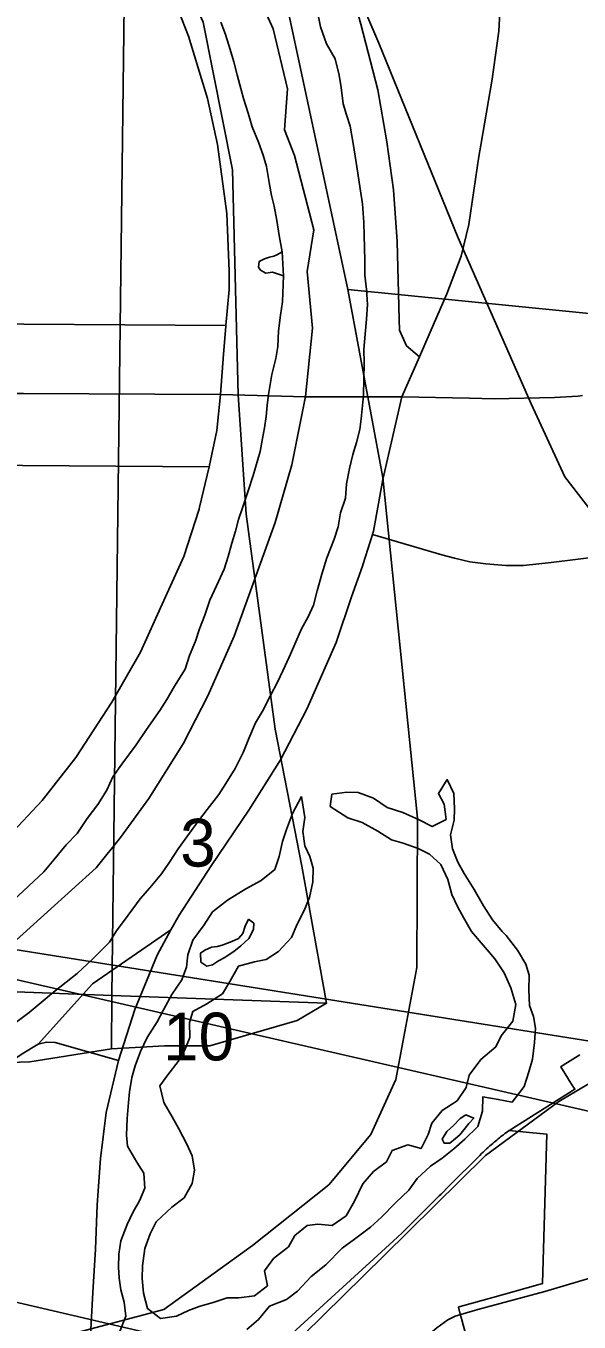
# Model space of a CAD drawing. Extents: x 0 to 34, y 0 to 22.
# Drawn here: x 5.94 to 6.424, y 16.149 to 17.285 of the extents above; entities that cross this region are included whole.
import ezdxf

# ---------------------------------------------------------------- set-up
doc = ezdxf.new("R2010")
doc.units = 0
for name, color, linetype in [('GM_X_City_Street', 7, 'Continuous'), ('GM_X_Corporation', 7, 'Continuous'), ('GM_X_County_Road', 7, 'Continuous'), ('GM_X_Major_River', 7, 'Continuous'), ('GM_X_Minor_Lake', 7, 'Continuous'), ('GM_X_Rail_Line', 7, 'Continuous'), ('GM_X_Section', 7, 'Continuous'), ('GM_X_Section_Text', 7, 'Continuous'), ('GM_X_State_Route', 7, 'Continuous'), ('GM_X_Township_Road', 7, 'Continuous'), ('SH_Text', 7, 'Continuous')]:
    doc.layers.add(name, color=color, linetype=linetype)

msp = doc.modelspace()

# ---------------------------------------------------------------- linework, layer by layer
at = {"layer": 'GM_X_City_Street'}
msp.add_line((6.2692, 16.9601), (6.3283, 16.9588), dxfattribs=at)
for points in [[(6.2667, 17.0282), (6.2651, 17.0961), (6.2619, 17.1413), (6.2559, 17.1835), (6.2479, 17.2291), (6.2332, 17.2866), (6.2208, 17.3307), (6.2057, 17.3695), (6.1994, 17.3856), (6.167, 17.4375), (6.1424, 17.4763), (6.0844, 17.5737), (6.0399, 17.6695), (6.0364, 17.6779), (6.0205, 17.716)], [(6.1148, 17.0215), (6.1149, 17.0225), (6.1177, 17.0542), (6.1178, 17.0702), (6.1157, 17.1206), (6.1076, 17.1813), (6.0989, 17.2215), (6.0821, 17.2761), (6.0569, 17.3412)], [(5.6157, 17.0314), (5.6206, 17.0277), (5.6254, 17.024), (5.6872, 17.0254), (5.8138, 17.025), (5.938, 17.0236), (6.1149, 17.0225)], [(6.1103, 16.9619), (6.1128, 16.9973), (6.1148, 17.0215)], [(6.2845, 16.9951), (6.2733, 17.0046), (6.2669, 17.0183), (6.2667, 17.0282)], [(5.813, 16.9637), (5.9115, 16.9629), (5.9375, 16.9628), (6.1103, 16.9619)], [(6.0919, 16.8634), (6.1003, 16.8985), (6.1069, 16.9304), (6.1103, 16.9619)], [(6.1103, 16.9619), (6.1849, 16.9599), (6.2692, 16.9601)], [(6.3283, 16.9588), (6.35, 16.9583), (6.4028, 16.9594), (6.4234, 16.9605), (6.4273, 16.9611)], [(5.6258, 16.9043), (5.8116, 16.9012), (5.9368, 16.8998), (6.1003, 16.8985)], [(5.5538, 16.5337), (5.5663, 16.5354), (5.5855, 16.5344), (5.5977, 16.5337), (5.606, 16.5333), (5.7039, 16.5242), (5.7775, 16.52), (5.8216, 16.5178), (5.8447, 16.5199), (5.8678, 16.5304), (5.8867, 16.543), (5.9245, 16.5746), (5.954, 16.6061), (5.9834, 16.6439), (6.0149, 16.6922), (6.0401, 16.7363), (6.059, 16.7783), (6.078, 16.8199), (6.0914, 16.8614), (6.0919, 16.8634)], [(6.2435, 16.8392), (6.304, 16.8215), (6.3153, 16.8187), (6.3285, 16.8154), (6.3427, 16.8135), (6.3601, 16.8121), (6.3757, 16.8121), (6.3998, 16.8149), (6.4852, 16.8253), (6.5792, 16.8385)], [(6.0668, 16.4928), (5.9982, 16.4455), (5.9505, 16.3926)], [(5.2425, 16.2183), (5.2513, 16.2216), (5.2602, 16.2223), (5.2843, 16.2201), (5.3467, 16.2161), (5.4122, 16.2135), (5.4393, 16.2119), (5.4499, 16.2113), (5.4915, 16.2125), (5.5278, 16.2165), (5.5628, 16.2224), (5.6238, 16.2341), (5.6759, 16.2485), (5.7191, 16.2629), (5.7839, 16.2907), (5.8093, 16.3036), (5.8399, 16.3198), (5.8867, 16.349), (5.9181, 16.3715), (5.9366, 16.3841), (5.9505, 16.3926), (5.9577, 16.3944), (5.9654, 16.394), (6.021, 16.3782)], [(6.3432, 16.162), (6.3943, 16.1757), (6.4318, 16.1867), (6.4582, 16.1974), (6.4798, 16.2098), (6.5079, 16.2262), (6.5312, 16.2404), (6.5539, 16.252), (6.5654, 16.2551), (6.577, 16.2574), (6.5936, 16.2577), (6.6025, 16.2574)], [(6.0364, 15.8874), (6.0374, 15.8877), (6.1029, 15.909), (6.1175, 15.9145), (6.1293, 15.9201), (6.1457, 15.9324), (6.1594, 15.9456), (6.1736, 15.9638), (6.2061, 16.0119), (6.2305, 16.0456), (6.2615, 16.0919), (6.2892, 16.1327), (6.294, 16.1389), (6.2996, 16.1438), (6.3093, 16.151), (6.3158, 16.1541), (6.3355, 16.1599), (6.3432, 16.162)]]:
    msp.add_lwpolyline(points, dxfattribs=at)
at = {"layer": 'GM_X_Corporation'}
msp.add_lwpolyline([(6.3291, 16.1231), (6.322, 16.1496), (6.3218, 16.15), (6.3203, 16.1558), (6.3203, 16.1559), (6.3186, 16.162), (6.3193, 16.1623), (6.3201, 16.1625), (6.3488, 16.1705), (6.3882, 16.1815), (6.3922, 16.1827), (6.3952, 16.2836), (6.3958, 16.304), (6.3961, 16.3136), (6.3808, 16.3152), (6.3632, 16.317), (6.3651, 16.3181), (6.3692, 16.3207), (6.3748, 16.3243), (6.4207, 16.353), (6.419, 16.3556), (6.4152, 16.3617), (6.4152, 16.3618), (6.4145, 16.3628), (6.4083, 16.3728), (6.4103, 16.374), (6.4103, 16.374), (6.4251, 16.3833)], dxfattribs=at)
at = {"layer": 'GM_X_County_Road'}
msp.add_line((6.2853, 16.997), (6.2938, 17.0166), dxfattribs=at)
for points in [[(6.3382, 17.1806), (6.3481, 17.2383), (6.3541, 17.2805), (6.3564, 17.3255), (6.3577, 17.3607), (6.3586, 17.3855), (6.3588, 17.3905)], [(6.2938, 17.0166), (6.3084, 17.0502), (6.3209, 17.0833), (6.3278, 17.1109), (6.3365, 17.1706), (6.3382, 17.1806)], [(6.2441, 16.8422), (6.2525, 16.8876), (6.2692, 16.9601), (6.2845, 16.9951), (6.2853, 16.997)], [(6.2353, 16.8135), (6.2435, 16.8392), (6.2441, 16.8422)], [(5.9955, 16.1334), (5.9962, 16.1373), (5.9985, 16.1748), (6.0008, 16.2128), (6.0023, 16.2516), (6.0052, 16.2923), (6.0102, 16.3326), (6.021, 16.3782), (6.0353, 16.4229), (6.0546, 16.4706), (6.0668, 16.4928), (6.0739, 16.5057), (6.102, 16.5489), (6.135, 16.5976), (6.1627, 16.6419), (6.1859, 16.6862), (6.2115, 16.7447), (6.2251, 16.7847), (6.2347, 16.8116), (6.2353, 16.8135)]]:
    msp.add_lwpolyline(points, dxfattribs=at)
at = {"layer": 'GM_X_Major_River'}
msp.add_line((6.1653, 17.0661), (6.1642, 17.087), dxfattribs=at)
for points in [[(5.9426, 16.4203), (5.953, 16.4292), (5.9638, 16.4381), (5.975, 16.447), (5.9846, 16.4544), (5.9981, 16.4671), (6.0129, 16.482), (6.0191, 16.4918), (6.0292, 16.5056), (6.0398, 16.5199), (6.0483, 16.5296), (6.0584, 16.5419), (6.0654, 16.5521), (6.0732, 16.5637), (6.083, 16.5776), (6.0908, 16.5884), (6.0986, 16.5982), (6.1087, 16.6113), (6.115, 16.6211), (6.1232, 16.6342), (6.1303, 16.6489), (6.1351, 16.6606), (6.141, 16.6741), (6.1469, 16.6843), (6.1536, 16.6975), (6.1603, 16.7103), (6.167, 16.7242), (6.1714, 16.7344), (6.1762, 16.7453), (6.1813, 16.7566), (6.1869, 16.7672), (6.1916, 16.7773), (6.1949, 16.7898), (6.199, 16.8046), (6.2034, 16.8189), (6.2098, 16.8351), (6.2134, 16.8461), (6.2152, 16.8582), (6.2196, 16.8711), (6.2206, 16.8836), (6.2232, 16.8972), (6.226, 16.9093), (6.2293, 16.9199), (6.2322, 16.9313), (6.2335, 16.9408), (6.2354, 16.9612), (6.236, 16.9898), (6.2358, 17.0015), (6.2368, 17.0148), (6.2382, 17.0281), (6.2389, 17.041), (6.238, 17.054), (6.2367, 17.0665), (6.2366, 17.0791), (6.2364, 17.0909), (6.2362, 17.1012), (6.2357, 17.1129), (6.2345, 17.1293), (6.2325, 17.1423), (6.2305, 17.156), (6.2281, 17.1709), (6.2264, 17.1819), (6.2237, 17.1972), (6.2205, 17.2072), (6.2176, 17.2167), (6.216, 17.2312), (6.2143, 17.2419), (6.2108, 17.2564), (6.2031, 17.2695), (6.1977, 17.2844), (6.1953, 17.2974)], [(6.1105, 17.2884), (6.1145, 17.2777), (6.1188, 17.2643), (6.122, 17.2536), (6.1248, 17.2421), (6.1304, 17.2215), (6.1344, 17.2085), (6.1379, 17.1966), (6.1434, 17.1832), (6.1477, 17.1717), (6.1505, 17.1618), (6.1529, 17.148), (6.155, 17.1366), (6.1571, 17.127), (6.1595, 17.1145), (6.1615, 17.1015), (6.1642, 17.087)], [(6.1642, 17.087), (6.1596, 17.0844), (6.157, 17.0833), (6.1532, 17.0823), (6.1489, 17.0808), (6.144, 17.0786), (6.1435, 17.0737), (6.1453, 17.071), (6.1498, 17.0683), (6.1559, 17.0693), (6.1653, 17.0661)], [(6.1653, 17.0661), (6.1645, 17.0433), (6.1628, 17.0315), (6.161, 17.0178), (6.1604, 17.0042), (6.1586, 16.9936), (6.1553, 16.9796), (6.1523, 16.9621), (6.151, 16.9523), (6.1501, 16.9428), (6.1487, 16.9329), (6.147, 16.9235), (6.1449, 16.9121), (6.1388, 16.8909), (6.1344, 16.8777), (6.1295, 16.8626), (6.1259, 16.8524), (6.1234, 16.8422), (6.1202, 16.8316), (6.1169, 16.8199), (6.1133, 16.8089), (6.1066, 16.7942), (6.101, 16.7818), (6.0966, 16.7686), (6.0918, 16.7565), (6.0882, 16.7459), (6.083, 16.7331), (6.0794, 16.7214), (6.07, 16.7063), (6.0633, 16.6947), (6.057, 16.6849), (6.0453, 16.6684), (6.0363, 16.6549), (6.0239, 16.6381), (6.016, 16.6268), (6.0105, 16.6151), (6.0027, 16.6027), (5.9933, 16.5904), (5.9847, 16.5772), (5.975, 16.5672), (5.9642, 16.5541), (5.9556, 16.5436), (5.9421, 16.5309), (5.9286, 16.5186)], [(5.9218, 16.4047), (5.9426, 16.4203)]]:
    msp.add_lwpolyline(points, dxfattribs=at)
at = {"layer": 'GM_X_Minor_Lake'}
for points in [[(6.3605, 16.4877), (6.3571, 16.4912), (6.3486, 16.5016), (6.3405, 16.5139), (6.3324, 16.5282), (6.3236, 16.542), (6.3181, 16.552), (6.3134, 16.5639), (6.3118, 16.5761), (6.315, 16.589), (6.3152, 16.5988), (6.3147, 16.6122), (6.3089, 16.6244), (6.3011, 16.6124), (6.3062, 16.6028), (6.3078, 16.5895), (6.2956, 16.5833), (6.2843, 16.5892), (6.27, 16.5956), (6.2561, 16.6), (6.2441, 16.6082), (6.2309, 16.6131), (6.221, 16.6133), (6.2077, 16.6116), (6.2064, 16.601), (6.2217, 16.5908), (6.2342, 16.5868), (6.2481, 16.5793), (6.2601, 16.5718), (6.2703, 16.5686), (6.2834, 16.5641), (6.2932, 16.559), (6.3033, 16.55), (6.3095, 16.537), (6.313, 16.5236), (6.3177, 16.5132), (6.3232, 16.5036), (6.3302, 16.4913), (6.3421, 16.4774), (6.3506, 16.4674), (6.3587, 16.455), (6.3645, 16.442), (6.3688, 16.4274), (6.3662, 16.4127), (6.3561, 16.3999), (6.3514, 16.3902), (6.3383, 16.379), (6.3281, 16.3655), (6.3253, 16.3545), (6.3175, 16.3429), (6.3044, 16.3344), (6.2954, 16.3232), (6.2922, 16.3134), (6.2859, 16.301), (6.2742, 16.3042), (6.2605, 16.2992), (6.2557, 16.2894), (6.2442, 16.2809), (6.2348, 16.27), (6.2277, 16.255), (6.2203, 16.2422), (6.208, 16.2337), (6.1955, 16.2347), (6.186, 16.2337), (6.1752, 16.2248), (6.1697, 16.215), (6.1566, 16.2046), (6.1488, 16.1938), (6.1515, 16.1808), (6.14, 16.1719), (6.1263, 16.1703), (6.116, 16.1701), (6.1046, 16.1665), (6.0916, 16.1626), (6.0821, 16.159), (6.0717, 16.1542), (6.0577, 16.1522), (6.0464, 16.1608), (6.0429, 16.1742), (6.0416, 16.1871), (6.0419, 16.1982), (6.044, 16.2133), (6.0485, 16.2262), (6.054, 16.2367), (6.0675, 16.2497), (6.0783, 16.2579), (6.0854, 16.2703), (6.0875, 16.2821), (6.0855, 16.2946), (6.0807, 16.305), (6.0738, 16.3184), (6.0679, 16.3288), (6.0606, 16.3415), (6.0571, 16.356), (6.0641, 16.3658), (6.073, 16.3774), (6.0789, 16.3875), (6.0833, 16.3985), (6.0832, 16.4114), (6.086, 16.4212), (6.0983, 16.4278)], [(6.1811, 16.6095), (6.1733, 16.5948), (6.1681, 16.5808), (6.1644, 16.5703), (6.1615, 16.557), (6.1579, 16.5457), (6.1459, 16.536), (6.1325, 16.5287), (6.1164, 16.5187), (6.1033, 16.5084), (6.0959, 16.4971), (6.0861, 16.4836), (6.0817, 16.4708), (6.0803, 16.4601), (6.0763, 16.4488), (6.0677, 16.4361), (6.0603, 16.4225), (6.0547, 16.412), (6.0461, 16.3985), (6.0402, 16.386), (6.0354, 16.3736), (6.0325, 16.3634), (6.0304, 16.3509), (6.0295, 16.3414), (6.0284, 16.3273), (6.0278, 16.3129), (6.0287, 16.303), (6.0368, 16.2891), (6.0431, 16.2795), (6.0439, 16.2662), (6.0392, 16.2552), (6.0337, 16.2455), (6.0285, 16.2345), (6.0229, 16.2202), (6.0212, 16.2085), (6.021, 16.197), (6.0215, 16.1875), (6.0229, 16.1772), (6.0257, 16.1665), (6.0273, 16.154), (6.0218, 16.14)], [(6.0983, 16.4278), (6.1121, 16.4367), (6.1184, 16.4476), (6.1259, 16.4608), (6.14, 16.4647), (6.1503, 16.4667), (6.161, 16.4738), (6.1723, 16.4861), (6.1774, 16.4978), (6.1834, 16.5098), (6.1881, 16.5211), (6.1911, 16.5348), (6.1913, 16.5469), (6.1885, 16.5569), (6.1841, 16.5665), (6.1824, 16.579), (6.1842, 16.5912), (6.1811, 16.6095)], [(6.1346, 16.502), (6.1319, 16.496), (6.1299, 16.4896), (6.126, 16.4851), (6.1202, 16.4825), (6.1126, 16.4797), (6.1076, 16.4782), (6.1023, 16.4776), (6.0966, 16.475), (6.0927, 16.4724), (6.0929, 16.4645), (6.0982, 16.4609), (6.1031, 16.462), (6.1085, 16.4657)], [(6.1085, 16.4657), (6.1139, 16.4686), (6.1177, 16.4712), (6.122, 16.4738), (6.1281, 16.4786), (6.1351, 16.4853), (6.139, 16.4932), (6.1395, 16.4985), (6.1346, 16.502)], [(6.1333, 16.1424), (6.1434, 16.1513), (6.1531, 16.1629), (6.168, 16.1687), (6.1776, 16.1761), (6.1896, 16.1888), (6.2024, 16.1992), (6.2167, 16.2137), (6.2275, 16.2215), (6.2417, 16.2322), (6.2513, 16.2408), (6.2634, 16.2535), (6.2753, 16.2647), (6.2824, 16.2748), (6.2943, 16.2856), (6.3043, 16.2926), (6.3147, 16.3008), (6.3244, 16.3093), (6.3356, 16.3205), (6.3397, 16.3337), (6.3399, 16.3463), (6.3535, 16.3441), (6.3656, 16.3416), (6.3761, 16.3554), (6.3802, 16.3683), (6.3834, 16.3793), (6.3852, 16.394), (6.3862, 16.4066), (6.3845, 16.4169), (6.3809, 16.4264), (6.3804, 16.4401), (6.3807, 16.4531), (6.3778, 16.4626), (6.3705, 16.4749), (6.3605, 16.4877)], [(6.3252, 16.3306), (6.3202, 16.3273), (6.3144, 16.3213), (6.3086, 16.3161), (6.3043, 16.3093), (6.3061, 16.3059), (6.311, 16.3058), (6.3161, 16.3099)], [(6.3161, 16.3099), (6.3199, 16.3132), (6.3246, 16.3188), (6.3277, 16.3229), (6.332, 16.3278), (6.3252, 16.3306)]]:
    msp.add_lwpolyline(points, dxfattribs=at)
at = {"layer": 'GM_X_Rail_Line'}
for points in [[(6.4409, 16.8524), (6.4119, 16.8899), (6.3824, 16.9538), (6.3182, 17.1), (6.2489, 17.2701), (6.1917, 17.404), (6.1478, 17.4778), (6.1062, 17.5367), (6.0851, 17.5704), (6.0495, 17.6501), (5.9772, 17.794), (5.9463, 17.8569), (5.94, 17.8766), (5.9404, 17.8883), (5.9424, 17.8993), (5.9505, 17.9228), (5.9579, 17.9295), (5.9682, 17.9321), (5.9914, 17.9329), (6.0459, 17.919), (6.0834, 17.9142), (6.1264, 17.9184), (6.1909, 17.9323), (6.2268, 17.9396)], [(6.165, 16.1203), (6.2534, 16.207), (6.3425, 16.2949), (6.4066, 16.3422), (6.4661, 16.3777), (6.5056, 16.3891), (6.5675, 16.4045), (6.5893, 16.4128), (6.6117, 16.4363), (6.6216, 16.4868), (6.6133, 16.6376), (6.5924, 16.7713)]]:
    msp.add_lwpolyline(points, dxfattribs=at)
at = {"layer": 'GM_X_Section'}
for points in [[(6.1181, 18.0687), (7.0966, 17.983), (7.0031, 16.9763), (6.2217, 17.0542), (6.1566, 17.3584), (6.0732, 17.5126)], [(5.0461, 17.3925), (6.0266, 17.3737), (6.0151, 16.4351), (5.016, 16.4735)], [(6.0266, 17.3737), (6.0573, 17.3724), (6.0951, 17.2884), (6.1207, 17.1591), (6.1257, 16.9617), (6.1328, 16.8571), (6.1581, 16.6687), (6.1816, 16.5486), (6.2032, 16.4285), (6.0151, 16.4351)], [(6.2217, 17.0542), (7.0031, 16.9763), (6.9063, 15.9571), (5.9113, 16.0496), (5.9234, 16.1293), (5.9728, 16.1367), (6.0607, 16.16), (6.1382, 16.2162), (6.2051, 16.2691), (6.2419, 16.3134), (6.2637, 16.3615), (6.2822, 16.4596), (6.2827, 16.5907), (6.2524, 16.8893)], [(5.0144, 16.4489), (5.016, 16.4735), (6.0151, 16.4351), (6.0146, 16.3885), (5.9432, 16.377), (5.8075, 16.3727), (5.6552, 16.351), (5.5604, 16.3194), (5.487, 16.3238), (5.3526, 16.3472), (5.2613, 16.3655), (5.1009, 16.4163)], [(6.0151, 16.4351), (6.2032, 16.4285), (6.1773, 16.4133), (6.1008, 16.3911), (6.0611, 16.3911), (6.0146, 16.3885)]]:
    msp.add_lwpolyline(points, close=True, dxfattribs=at)
at = {"layer": 'GM_X_State_Route'}
msp.add_lwpolyline([(6.163, 16.13), (6.2614, 16.2199), (6.2695, 16.2273), (6.3018, 16.2596), (6.3034, 16.2612), (6.3106, 16.2683), (6.3373, 16.295), (6.3389, 16.2966), (6.3403, 16.2979), (6.3419, 16.2994), (6.3433, 16.3008), (6.3448, 16.3021), (6.3461, 16.3033), (6.3474, 16.3044), (6.3488, 16.3056), (6.35, 16.3066), (6.351, 16.3075), (6.3522, 16.3085), (6.3534, 16.3095), (6.3545, 16.3104), (6.3556, 16.3112), (6.3568, 16.3122), (6.3581, 16.3132), (6.3593, 16.3141), (6.3608, 16.3152), (6.362, 16.3161), (6.3632, 16.317), (6.3651, 16.3181), (6.3692, 16.3207), (6.3748, 16.3243), (6.4207, 16.353), (6.419, 16.3556), (6.4152, 16.3617), (6.4152, 16.3618), (6.4145, 16.3628), (6.4083, 16.3728), (6.4103, 16.374), (6.4251, 16.3833)], dxfattribs=at)
at = {"layer": 'GM_X_Township_Road'}
for points in [[(5.8944, 16.4506), (6.0012, 16.547), (6.0226, 16.5736), (6.0475, 16.6079), (6.0775, 16.6559), (6.099, 16.6979), (6.1221, 16.7502), (6.1581, 16.8497), (6.1727, 16.9003), (6.1846, 16.9604), (6.1907, 17.0203), (6.1862, 17.0698), (6.192, 17.1065), (6.1749, 17.1716), (6.1663, 17.1939), (6.1689, 17.2299), (6.1564, 17.2827), (6.1384, 17.3221)], [(6.1384, 17.3221), (6.1564, 17.2827), (6.1689, 17.2299), (6.1663, 17.1939), (6.1749, 17.1716), (6.192, 17.1065), (6.1862, 17.0698), (6.1907, 17.0203), (6.1846, 16.9604), (6.1727, 16.9003), (6.1581, 16.8497), (6.1221, 16.7502), (6.099, 16.6979), (6.0775, 16.6559), (6.0475, 16.6079), (6.0226, 16.5736), (6.0012, 16.547), (5.8944, 16.4506)]]:
    msp.add_lwpolyline(points, dxfattribs=at)
at = {"layer": 'SH_Text'}
for points in [[(5.5598, 16.5345), (9.346, 15.9306), (10.7296, 15.939), (10.7249, 15.654), (9.3684, 15.6583)], [(5.4805, 16.2716), (9.333, 15.3718), (10.6987, 15.3733), (10.6963, 15.0992), (9.3554, 15.0994)]]:
    msp.add_lwpolyline(points, close=True, dxfattribs=at)

# ---------------------------------------------------------------- texts
at = {"layer": 'GM_X_Section_Text'}
for s, height, p in [('3', 0.0419, (6.0749, 16.5482)), ('10', 0.04186, (6.0599, 16.3783))]:
    msp.add_text(s, height=height, rotation=0, dxfattribs=at).set_placement(p)

doc.saveas('drawing.dxf')
